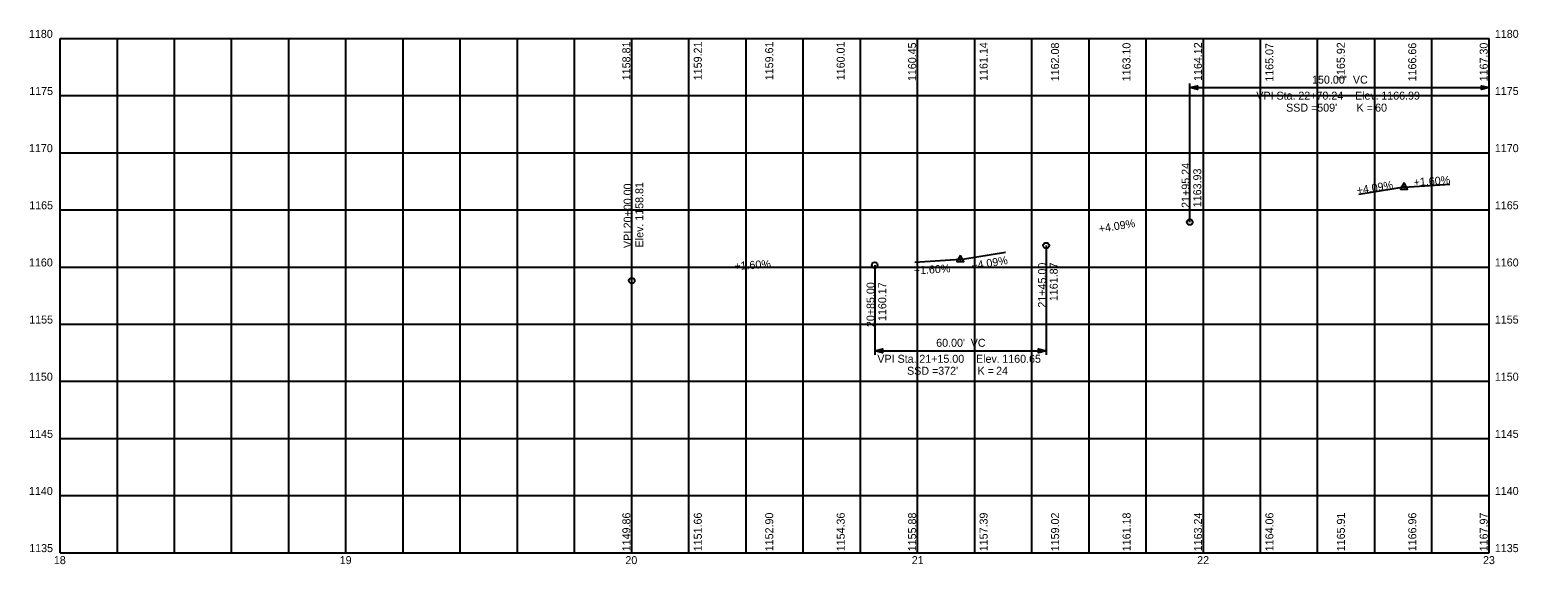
# Model space of a CAD drawing. Extents: x -211 to 310, y 1131 to 1318.
import ezdxf

# ---------------------------------------------------------------- set-up
doc = ezdxf.new("R2010")
doc.units = 0
for name, color, linetype in [('PF_P_Sta_Elev_Text', 7, 'Continuous'), ('PF_P_Text', 7, 'Continuous'), ('PF_P_Text_Curve', 7, 'Continuous'), ('PF_P_Text_Grade', 7, 'Continuous'), ('PF_P_Text_Points', 7, 'Continuous'), ('PF_P_Text_Strip_Grades_20', 7, 'Continuous'), ('PF_X_Text_Strip_Grade', 7, 'Continuous'), ('SH_Major_Grid_Line', 7, 'Continuous')]:
    doc.layers.add(name, color=color, linetype=linetype)

msp = doc.modelspace()

# ---------------------------------------------------------------- linework, layer by layer
at = {"layer": 'PF_P_Text'}
for points in [[(270.24, 1264.42), (268.99, 1262.26), (271.49, 1262.26)], [(115, 1239.04), (113.75, 1236.87), (116.25, 1236.87)]]:
    msp.add_lwpolyline(points, close=True, dxfattribs=at)
at = {"layer": 'PF_P_Text_Curve'}
for p, q in [((195.24, 1250.71), (195.24, 1299.18)), ((195.24, 1297.88), (195.24, 1297.68)), ((195.24, 1297.78), (300, 1297.78)), ((300, 1297.68), (300, 1297.88)), ((145, 1242.5), (145, 1204.27)), ((85, 1235.67), (85, 1204.27)), ((85, 1205.77), (85, 1205.57)), ((85, 1205.67), (145, 1205.67)), ((145, 1205.57), (145, 1205.77))]:
    msp.add_line(p, q, dxfattribs=at)
for points in [[(195.24, 1297.78), (197.96, 1298.46), (197.96, 1297.1)], [(300, 1297.78), (297.28, 1297.1), (297.28, 1298.46)], [(85, 1205.67), (87.72, 1206.35), (87.72, 1204.99)], [(145, 1205.67), (142.28, 1204.99), (142.28, 1206.35)]]:
    msp.add_lwpolyline(points, close=True, dxfattribs=at)
for centre in [(195.24, 1250.71), (145, 1242.5), (85, 1235.67)]:
    msp.add_circle(centre, 1, dxfattribs=at)
at = {"layer": 'PF_P_Text_Grade'}
for p, q in [((270.24, 1262.98), (254.45, 1260.4)), ((270.24, 1262.98), (286.21, 1264)), ((270.24, 1262.98), (270.24, 1262.98)), ((115, 1237.59), (130.79, 1240.17)), ((115, 1237.59), (99.03, 1236.57)), ((115, 1237.59), (115, 1237.59))]:
    msp.add_line(p, q, dxfattribs=at)
for centre in [(270.24, 1262.98), (270.24, 1262.98), (115, 1237.59), (115, 1237.59)]:
    msp.add_circle(centre, 0.1, dxfattribs=at)
at = {"layer": 'PF_P_Text_Points'}
msp.add_line((0, 1230.23), (0, 1265.23), dxfattribs=at)
msp.add_circle((0, 1230.23), 1, dxfattribs=at)
at = {"layer": 'SH_Major_Grid_Line'}
for p, q in [((-200, 1315), (300, 1315)), ((-200, 1135), (-200, 1315)), ((-200, 1135), (-200, 1315)), ((-180, 1135), (-180, 1315)), ((-160, 1135), (-160, 1315)), ((-140, 1135), (-140, 1315)), ((-120, 1135), (-120, 1315)), ((-100, 1135), (-100, 1315)), ((-80, 1135), (-80, 1315)), ((-60, 1135), (-60, 1315)), ((-40, 1135), (-40, 1315)), ((-20, 1135), (-20, 1315)), ((0, 1135), (0, 1315)), ((20, 1135), (20, 1315)), ((40, 1135), (40, 1315)), ((60, 1135), (60, 1315)), ((80, 1135), (80, 1315)), ((100, 1135), (100, 1315)), ((120, 1135), (120, 1315)), ((140, 1135), (140, 1315)), ((160, 1135), (160, 1315)), ((180, 1135), (180, 1315)), ((200, 1135), (200, 1315)), ((220, 1135), (220, 1315)), ((240, 1135), (240, 1315)), ((260, 1135), (260, 1315)), ((280, 1135), (280, 1315)), ((300, 1135), (300, 1315)), ((-200, 1295), (300, 1295)), ((-200, 1275), (300, 1275)), ((-200, 1255), (300, 1255)), ((-200, 1235), (300, 1235)), ((-200, 1215), (300, 1215)), ((-200, 1195), (300, 1195)), ((-200, 1175), (300, 1175)), ((-200, 1155), (300, 1155)), ((-200, 1135), (300, 1135))]:
    msp.add_line(p, q, dxfattribs=at)

# ---------------------------------------------------------------- texts
at = {"layer": 'PF_P_Sta_Elev_Text'}
for s, p in [('1180', (-210.93, 1315.2)), ('1180', (302, 1315.2)), ('1175', (-210.84, 1295.2)), ('1175', (302, 1295.2)), ('1170', (-210.93, 1275.2)), ('1170', (302, 1275.2)), ('1165', (-210.84, 1255.2)), ('1165', (302, 1255.2)), ('1160', (-210.93, 1235.2)), ('1160', (302, 1235.2)), ('1155', (-210.84, 1215.2)), ('1155', (302, 1215.2)), ('1150', (-210.93, 1195.2)), ('1150', (302, 1195.2)), ('1145', (-210.84, 1175.2)), ('1145', (302, 1175.2)), ('1140', (-210.93, 1155.2)), ('1140', (302, 1155.2)), ('1135', (-210.84, 1135.2)), ('1135', (302, 1135.2)), ('18', (-202.22, 1131)), ('19', (-102.2, 1131)), ('20', (-2.23, 1131)), ('21', (97.97, 1131)), ('22', (197.84, 1131)), ('23', (297.85, 1131))]:
    msp.add_text(s, height=2.8, dxfattribs=at).set_placement(p)
at = {"layer": 'PF_P_Text_Curve'}
for s, p in [("150.00'", (238.03, 1299.18)), (' VC', (251.29, 1299.18)), ('VPI Sta. ', (218.53, 1293.58)), ('SSD = ', (228.95, 1289.38)), ('22+70.24', (233.22, 1293.58)), ("509'", (239.85, 1289.38)), ('   Elev. ', (249.94, 1293.58)), ('K = ', (253.62, 1289.38)), ('60', (260.1, 1289.38)), ('1166.99', (262.25, 1293.58)), ("60.00'", (106.52, 1207.07)), (' VC', (117.55, 1207.07)), ('VPI Sta. ', (85.93, 1201.47)), ('21+15.00', (100.61, 1201.47)), ('   Elev. ', (117.33, 1201.47)), ('1160.65', (129.64, 1201.47)), ('SSD = ', (96.33, 1197.27)), ("372'", (107.23, 1197.27)), ('K = ', (121, 1197.27)), ('24', (127.48, 1197.27))]:
    msp.add_text(s, height=2.8, dxfattribs=at).set_placement(p)
at = {"layer": 'PF_P_Text_Grade'}
for s, rotation, p in [('+1.60%', 3.6619, (273.68, 1263.28)), ('+4.09%', 9.2877, (253.9, 1260.39)), ('+4.09%', 9.2877, (163.66, 1246.95)), ('+1.60%', 3.6619, (35.97, 1233.93)), ('+1.60%', 3.6619, (98.76, 1232.34)), ('+4.09%', 9.2877, (119.09, 1234))]:
    msp.add_text(s, height=2.8, rotation=rotation, dxfattribs=at).set_placement(p)
at = {"layer": 'PF_P_Text_Points'}
for s, p in [('21+95.24', (195.2, 1255.71)), ('1163.93', (199.27, 1255.92)), ('20+00.00', (-0.04, 1248.52)), ('1158.81', (4.05, 1251.19)), ('VPI ', (-0.04, 1241.63)), ('Elev. ', (4.05, 1241.87)), ('21+45.00', (144.96, 1220.79)), ('1161.87', (149.03, 1223.05)), ('20+85.00', (84.96, 1213.96)), ('1160.17', (89.05, 1216.1))]:
    msp.add_text(s, height=2.8, rotation=90, dxfattribs=at).set_placement(p)
at = {"layer": 'PF_P_Text_Strip_Grades_20'}
for s, p in [('1158.81', (-0.5, 1300.38)), ('1159.21', (24.5, 1300.38)), ('1159.61', (49.5, 1300.38)), ('1160.01', (74.5, 1300.38)), ('1160.45', (99.5, 1300.07)), ('1161.14', (124.5, 1300.14)), ('1162.08', (149.51, 1300.01)), ('1163.10', (174.51, 1299.99)), ('1164.12', (199.51, 1300.12)), ('1165.07', (224.51, 1299.85)), ('1165.92', (249.5, 1300.12)), ('1166.66', (274.5, 1299.96)), ('1167.30', (299.5, 1299.99))]:
    msp.add_text(s, height=2.8, rotation=90, dxfattribs=at).set_placement(p)
at = {"layer": 'PF_X_Text_Strip_Grade'}
for s, p in [('1149.86', (-0.48, 1135.5)), ('1151.66', (24.51, 1135.5)), ('1152.90', (49.51, 1135.5)), ('1154.36', (74.51, 1135.5)), ('1155.88', (99.51, 1135.5)), ('1157.39', (124.51, 1135.5)), ('1159.02', (149.53, 1135.5)), ('1161.18', (174.53, 1135.5)), ('1163.24', (199.52, 1135.5)), ('1164.06', (224.52, 1135.5)), ('1165.91', (249.52, 1135.5)), ('1166.96', (274.51, 1135.5)), ('1167.97', (299.5, 1135.5))]:
    msp.add_text(s, height=2.8, rotation=90, dxfattribs=at).set_placement(p)

doc.saveas('drawing.dxf')
